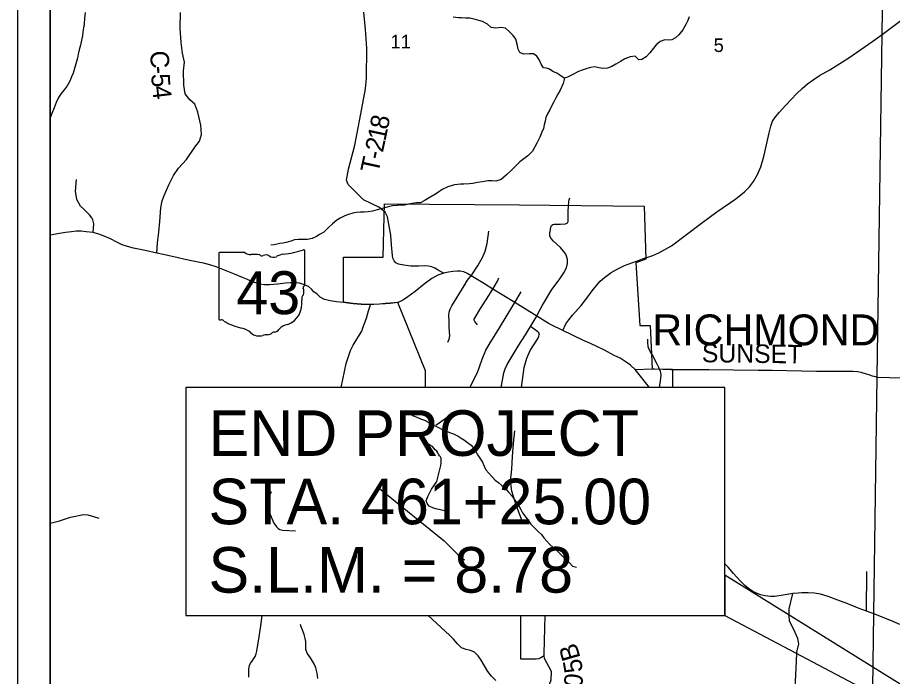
# Model space of a CAD drawing. Extents: x 0 to 34, y 0 to 22.
# Drawn here: x 2 to 4.685, y 18.266 to 20.29 of the extents above; entities that cross this region are included whole.
import ezdxf

# ---------------------------------------------------------------- set-up
doc = ezdxf.new("R2010")
doc.units = 0
for name, color, linetype in [('GM_X_City_Street', 7, 'Continuous'), ('GM_X_Corporation', 7, 'Continuous'), ('GM_X_Corporation_Text', 7, 'Continuous'), ('GM_X_County_Road', 7, 'Continuous'), ('GM_X_County_Road_Text', 7, 'Continuous'), ('GM_X_Minor_River', 7, 'Continuous'), ('GM_X_Section_Text', 7, 'Continuous'), ('GM_X_State_Location', 7, 'Continuous'), ('GM_X_State_Route', 7, 'Continuous'), ('GM_X_State_Shield', 7, 'Continuous'), ('GM_X_Township_Road', 7, 'Continuous'), ('GM_X_Township_Road_Text', 7, 'Continuous'), ('SH_Data', 7, 'Continuous'), ('SH_Text', 7, 'Continuous')]:
    doc.layers.add(name, color=color, linetype=linetype)

msp = doc.modelspace()

# ---------------------------------------------------------------- linework, layer by layer
at = {"layer": 'GM_X_City_Street'}
msp.add_line((3.5265, 19.4141), (3.5459, 19.447), dxfattribs=at)
for points in [[(3.4846, 19.1536), (3.4924, 19.1981), (3.4962, 19.2112), (3.503, 19.2244), (3.5365, 19.2801), (3.5585, 19.3154), (3.574, 19.3409), (3.5933, 19.3728), (3.6, 19.3862), (3.6114, 19.4065), (3.6402, 19.4546), (3.6625, 19.4844), (3.6769, 19.5054), (3.6847, 19.5208), (3.6881, 19.5342), (3.6883, 19.5462), (3.6858, 19.5542), (3.6832, 19.5631), (3.676, 19.5723), (3.666, 19.5839), (3.6452, 19.6034), (3.6374, 19.6109), (3.634, 19.6187), (3.6341, 19.6275), (3.6356, 19.6372), (3.6367, 19.6466), (3.639, 19.6514), (3.6429, 19.6542), (3.647, 19.6554), (3.6662, 19.6553), (3.6813, 19.6565), (3.6874, 19.659), (3.6899, 19.6636), (3.6902, 19.6691), (3.6902, 19.691), (3.6908, 19.7142), (3.6915, 19.7206), (3.6921, 19.7248), (3.6931, 19.7294), (3.6951, 19.7355)], [(3.308, 19.505), (3.2997, 19.5083), (3.2906, 19.5134), (3.281, 19.5195), (3.2718, 19.5241), (3.2614, 19.5263), (3.2502, 19.5271), (3.232, 19.5264), (3.2072, 19.5261), (3.1854, 19.5296), (3.1695, 19.5325), (3.1607, 19.5359), (3.1555, 19.5428), (3.1517, 19.5504), (3.1508, 19.5589), (3.1474, 19.5912), (3.1459, 19.6218), (3.1355, 19.6779)], [(3.3203, 19.293), (3.325, 19.3023), (3.3266, 19.3121), (3.3249, 19.3384), (3.3245, 19.3575), (3.3237, 19.3748), (3.3248, 19.3844), (3.3277, 19.3941), (3.3328, 19.4039), (3.3708, 19.4662), (3.3815, 19.4834), (3.3894, 19.4934), (3.3924, 19.4964), (3.4133, 19.5291), (3.4282, 19.5553), (3.4353, 19.5721), (3.4416, 19.5956), (3.4467, 19.6332)], [(3.4118, 19.3461), (3.404, 19.356), (3.4016, 19.3601), (3.4012, 19.3639), (3.421, 19.3958), (3.4392, 19.4246), (3.4586, 19.4558), (3.4732, 19.4805), (3.4773, 19.4903)], [(3.5469, 19.1536), (3.5553, 19.2151), (3.5627, 19.2436), (3.5733, 19.2668), (3.5974, 19.3053), (3.6001, 19.311), (3.6014, 19.3148), (3.6018, 19.3186), (3.5999, 19.3218), (3.5964, 19.3248), (3.574, 19.3409)]]:
    msp.add_lwpolyline(points, dxfattribs=at)
at = {"layer": 'GM_X_Corporation'}
for points in [[(4.6083, 17.0396), (4.6111, 17.2406), (4.6176, 17.7005), (4.6283, 18.459), (4.6386, 19.1863), (4.6534, 20.2382), (4.6627, 20.9), (2.1, 20.9), (2.1, 17.0396)], [(3.2523, 19.1536), (3.2519, 19.2051), (3.1667, 19.4149), (3.1438, 19.4123), (3.1289, 19.4114), (3.111, 19.4099), (3.0831, 19.4084), (3.0548, 19.4093), (3.0295, 19.4114), (3, 19.4152), (3.0007, 19.554), (3.1224, 19.5535), (3.1251, 19.6782), (3.1263, 19.7178), (3.5401, 19.7148), (3.6332, 19.713), (3.9236, 19.7105), (3.9285, 19.5472), (3.898, 19.5359), (3.9099, 19.3443), (3.9414, 19.3441), (3.9476, 19.2111), (4.0098, 19.2094), (4.0098, 19.1536)]]:
    msp.add_lwpolyline(points, dxfattribs=at)
at = {"layer": 'GM_X_County_Road'}
msp.add_line((3.9548, 19.2104), (4.005, 19.209), dxfattribs=at)
for points in [[(2.4276, 19.566), (2.4295, 19.5977), (2.4336, 19.6309), (2.4372, 19.6637), (2.44, 19.7048), (2.4437, 19.7263), (2.45, 19.7432), (2.4642, 19.7754), (2.4788, 19.8044), (2.4946, 19.8271), (2.5186, 19.854), (2.5445, 19.8914), (2.5589, 19.9096), (2.5649, 19.9302), (2.5624, 19.9586), (2.5536, 19.9991), (2.544, 20.0232), (2.5293, 20.0373), (2.5145, 20.0552), (2.5105, 20.0821), (2.5093, 20.1257), (2.5121, 20.1524), (2.5062, 20.1804), (2.5025, 20.2133), (2.4997, 20.2565), (2.4998, 20.3048)], [(3.8952, 19.2087), (3.9478, 19.2106), (3.9548, 19.2104)], [(4.005, 19.209), (4.01, 19.2088), (4.1215, 19.2085), (4.2726, 19.2064), (4.3156, 19.2063), (4.4068, 19.205), (4.4518, 19.2038), (4.5157, 19.204), (4.5647, 19.2034), (4.5789, 19.2025), (4.5881, 19.2005), (4.6045, 19.1954), (4.6127, 19.193), (4.6196, 19.1907), (4.6233, 19.1898)], [(4.6233, 19.1898), (4.6279, 19.1885), (4.6388, 19.1858), (4.7126, 19.1836)]]:
    msp.add_lwpolyline(points, dxfattribs=at)
at = {"layer": 'GM_X_Minor_River'}
for points in [[(2.2078, 20.3048), (2.2058, 20.2877), (2.2041, 20.269), (2.2028, 20.2576), (2.201, 20.2461), (2.1993, 20.2339), (2.1964, 20.2198), (2.1932, 20.2045), (2.1895, 20.19), (2.1863, 20.1767), (2.1838, 20.1652), (2.1794, 20.1476), (2.1754, 20.1331), (2.1707, 20.119), (2.1659, 20.1079), (2.1603, 20.0945), (2.1529, 20.0803), (2.1435, 20.068), (2.1342, 20.0561), (2.126, 20.0438), (2.1189, 20.0292), (2.1123, 20.0124), (2.1053, 19.9951), (2.1, 19.982)], [(4.0616, 20.2918), (4.0572, 20.2807), (4.0524, 20.27), (4.0416, 20.252), (4.03, 20.2369), (4.0191, 20.2269), (4.0085, 20.2214), (3.9975, 20.2197), (3.9864, 20.2211), (3.972, 20.2156), (3.9604, 20.2055), (3.9514, 20.1955), (3.9401, 20.1809), (3.9292, 20.1685), (3.916, 20.1604), (3.9065, 20.1602), (3.8957, 20.1711), (3.8802, 20.169), (3.8643, 20.1623), (3.8503, 20.1549), (3.8363, 20.1463), (3.8235, 20.1393), (3.8102, 20.1342), (3.7965, 20.1328), (3.7843, 20.1349), (3.7717, 20.1378), (3.758, 20.1365), (3.7448, 20.1325), (3.733, 20.1277), (3.7217, 20.1234), (3.7024, 20.1136), (3.688, 20.1069), (3.6774, 20.103), (3.6647, 20.1131), (3.6551, 20.119), (3.6429, 20.1242), (3.6329, 20.1309), (3.6234, 20.1346), (3.6138, 20.1356), (3.6068, 20.1469), (3.6021, 20.1583), (3.594, 20.1711), (3.5832, 20.1786), (3.5703, 20.1784), (3.5524, 20.1774), (3.5413, 20.1822), (3.537, 20.192), (3.533, 20.208), (3.529, 20.2227), (3.5209, 20.2348), (3.5085, 20.2464), (3.4977, 20.2566), (3.4848, 20.2594), (3.4681, 20.2565), (3.454, 20.2586), (3.4428, 20.2695), (3.4271, 20.2773), (3.4156, 20.2809), (3.4019, 20.2849), (3.3878, 20.2874), (3.3744, 20.288), (3.363, 20.2882), (3.3531, 20.2888), (3.3367, 20.2912)], [(3.6792, 20.1037), (3.675, 20.087), (3.6649, 20.0663), (3.6582, 20.0547), (3.6512, 20.0409), (3.6445, 20.0283), (3.6393, 20.0179), (3.6334, 20.0064), (3.6263, 19.9934), (3.6215, 19.9827), (3.619, 19.9716), (3.6168, 19.9597), (3.6139, 19.949), (3.6091, 19.9372), (3.6025, 19.9219), (3.5936, 19.9038), (3.5805, 19.8789), (3.5666, 19.865), (3.5538, 19.8561), (3.5421, 19.8468), (3.5305, 19.8356), (3.5162, 19.8209), (3.5008, 19.8066), (3.4842, 19.7926), (3.4676, 19.7867), (3.4569, 19.7885), (3.4436, 19.7879), (3.4269, 19.7854), (3.412, 19.7829), (3.3969, 19.78), (3.3874, 19.7791), (3.3695, 19.7781), (3.36, 19.7784), (3.341, 19.7758), (3.3307, 19.773), (3.3205, 19.7694), (3.3035, 19.762), (3.2922, 19.7538), (3.2805, 19.746), (3.2688, 19.739), (3.2582, 19.7332), (3.2476, 19.7265), (3.237, 19.7207), (3.2237, 19.7201), (3.2116, 19.7188), (3.2002, 19.7164), (3.1877, 19.7135), (3.1762, 19.7134), (3.1652, 19.7128), (3.1512, 19.7115), (3.1348, 19.7075), (3.1193, 19.7031), (3.1041, 19.6987), (3.0893, 19.6947), (3.0761, 19.693), (3.0643, 19.692), (3.0517, 19.6919), (3.0399, 19.6909), (3.0289, 19.6885), (3.016, 19.6849), (3.0043, 19.6805), (2.9907, 19.6735), (2.9805, 19.6673), (2.9665, 19.6564), (2.9534, 19.6437), (2.9399, 19.6309), (2.9289, 19.6247), (2.9176, 19.6169), (2.904, 19.611), (2.8903, 19.6078), (2.8762, 19.6076), (2.8618, 19.6078), (2.8504, 19.6068), (2.8386, 19.6032), (2.8242, 19.5992), (2.8147, 19.5972), (2.8048, 19.5956), (2.7874, 19.5919), (2.7775, 19.5902)], [(3.9333, 19.3015), (3.9334, 19.292), (3.9347, 19.2794), (3.9387, 19.2696), (3.9449, 19.2583), (3.9504, 19.2484), (3.9562, 19.2371), (3.9624, 19.2261), (3.9675, 19.2159), (3.9726, 19.2042), (3.9739, 19.192), (3.9733, 19.1817), (3.9695, 19.1536)], [(3.1915, 19.0827), (3.2027, 19.0733), (3.2149, 19.0663), (3.226, 19.0622), (3.2371, 19.0574), (3.2486, 19.053), (3.262, 19.046), (3.2742, 19.0389), (3.2915, 19.0304), (3.303, 19.0248), (3.3144, 19.0201), (3.3259, 19.0156), (3.3378, 19.0112), (3.3519, 19.0038), (3.3615, 18.9982), (3.3715, 18.9923), (3.3815, 18.9848), (3.3919, 18.9766), (3.4007, 18.9664), (3.4062, 18.9566), (3.4128, 18.9453), (3.4268, 18.9242), (3.4323, 18.9117), (3.437, 18.9011), (3.4462, 18.8909), (3.4555, 18.8804), (3.4663, 18.8695), (3.4767, 18.8609), (3.4867, 18.8531), (3.4963, 18.8441), (3.5067, 18.8324), (3.5168, 18.8211), (3.5238, 18.8109), (3.5315, 18.8008), (3.5389, 18.7898), (3.5443, 18.7793), (3.5502, 18.7683), (3.5591, 18.7566), (3.5668, 18.7465), (3.5754, 18.7344), (3.5842, 18.7246), (3.5981, 18.7111), (3.6081, 18.7018), (3.6155, 18.6916), (3.6244, 18.6814), (3.634, 18.6717), (3.644, 18.6623), (3.654, 18.6544), (3.6633, 18.6447), (3.6733, 18.6345), (3.6833, 18.6248), (3.6941, 18.6147), (3.7034, 18.6049), (3.7157, 18.6014)], [(3.4675, 18.254), (3.4548, 18.2671), (3.4436, 18.2814), (3.4327, 18.2992), (3.4226, 18.3165), (3.414, 18.3297), (3.4028, 18.341), (3.3902, 18.3461), (3.3772, 18.349), (3.3631, 18.3537), (3.3504, 18.3669), (3.3376, 18.3812), (3.3253, 18.3935), (3.2601, 18.4536)], [(2.9215, 18.2598), (2.9197, 18.2769), (2.9157, 18.2928), (2.9118, 18.3027), (2.9055, 18.3132), (2.8989, 18.3234), (2.8885, 18.3381), (2.8853, 18.3495), (2.8851, 18.3635), (2.8846, 18.3734), (2.8833, 18.3829), (2.8797, 18.3947), (2.8754, 18.4068), (2.871, 18.4185), (2.869, 18.4261)]]:
    msp.add_lwpolyline(points, dxfattribs=at)
at = {"layer": 'GM_X_State_Route'}
for points in [[(3.9496, 19.5592), (3.9687, 19.5667), (3.9862, 19.5776), (4.0066, 19.589), (4.0993, 19.6581), (4.1459, 19.6927), (4.2042, 19.733), (4.2309, 19.7545), (4.2469, 19.7694), (4.2589, 19.7858), (4.2711, 19.8081), (4.281, 19.8312), (4.2902, 19.8628), (4.2987, 19.8984), (4.3066, 19.9356), (4.3119, 19.9562), (4.3174, 19.9709), (4.326, 19.9845), (4.3386, 19.9995), (4.3558, 20.0184), (4.3739, 20.0382), (4.3912, 20.0561), (4.4077, 20.0714), (4.4249, 20.0862), (4.4418, 20.0985), (4.4611, 20.1112), (4.4927, 20.1293), (4.5515, 20.1661), (4.6251, 20.2166), (4.6536, 20.2377), (4.7192, 20.2863)], [(3.014, 19.4129), (3.0002, 19.4147), (2.9793, 19.4165), (2.9591, 19.4198), (2.9424, 19.4242), (2.9284, 19.4311), (2.9192, 19.4397), (2.9097, 19.4478), (2.9022, 19.4555), (2.893, 19.4632), (2.8805, 19.4686), (2.8659, 19.4737), (2.8548, 19.4751), (2.8462, 19.4754), (2.8365, 19.4754), (2.8227, 19.474), (2.7975, 19.4705), (2.7736, 19.4688), (2.7565, 19.469), (2.7433, 19.4712), (2.7313, 19.4745), (2.7203, 19.4782), (2.7054, 19.485), (2.6909, 19.4913), (2.6662, 19.5012), (2.6352, 19.5143), (2.6092, 19.5246), (2.5905, 19.5298), (2.5712, 19.5349), (2.5543, 19.5382), (2.5234, 19.5449), (2.4794, 19.5549), (2.4469, 19.562), (2.4276, 19.566), (2.3915, 19.5742), (2.3562, 19.5818), (2.3378, 19.5862), (2.3211, 19.5918), (2.3045, 19.5997), (2.2859, 19.6102), (2.2664, 19.6184), (2.2495, 19.6242), (2.2323, 19.6291), (2.2111, 19.6311), (2.1958, 19.6336), (2.1806, 19.6333), (2.1653, 19.6316), (2.1478, 19.6293), (2.1291, 19.6267), (2.1, 19.6216)], [(3.9023, 19.5426), (3.9183, 19.5482), (3.9409, 19.5559), (3.9496, 19.5592)], [(3.6733, 19.3285), (3.683, 19.3487), (3.6915, 19.3618), (3.7031, 19.3754), (3.7301, 19.4055), (3.7473, 19.4276), (3.7639, 19.4509), (3.7765, 19.4672), (3.788, 19.4798), (3.8013, 19.4914), (3.8218, 19.5064), (3.8424, 19.5184), (3.8632, 19.5285), (3.8854, 19.5366), (3.9023, 19.5426)], [(3.3819, 19.5029), (3.3811, 19.5035), (3.3702, 19.5084), (3.3589, 19.511), (3.349, 19.5111), (3.3356, 19.5095), (3.3222, 19.5075), (3.308, 19.505), (3.2899, 19.4989), (3.2712, 19.4882), (3.2479, 19.4704), (3.2205, 19.4486), (3.1978, 19.4317), (3.1846, 19.4224), (3.1811, 19.4208)], [(3.4331, 19.4714), (3.3924, 19.4964), (3.3819, 19.5029)], [(3.5265, 19.4141), (3.4586, 19.4558), (3.4331, 19.4714)], [(3.1811, 19.4208), (3.1669, 19.4144), (3.144, 19.4117), (3.1291, 19.4108), (3.1112, 19.4093), (3.0932, 19.4084)], [(3.0932, 19.4084), (3.0833, 19.4079), (3.055, 19.4088), (3.0297, 19.4108), (3.014, 19.4129)], [(3.388, 19.1536), (3.4117, 19.1998), (3.4177, 19.2171), (3.4256, 19.241), (3.4374, 19.2687), (3.4504, 19.2905), (3.4679, 19.3183), (3.4965, 19.3659), (3.5265, 19.4141)], [(3.6282, 19.351), (3.6179, 19.3569), (3.5933, 19.3728), (3.5265, 19.4141)], [(3.6733, 19.3285), (3.6377, 19.3457), (3.6282, 19.351)], [(3.7468, 19.2935), (3.7413, 19.2959), (3.7009, 19.315), (3.6733, 19.3285)], [(3.9396, 19.1536), (3.8952, 19.2087), (3.8811, 19.222), (3.8678, 19.2316), (3.8499, 19.2438), (3.8316, 19.2521), (3.8019, 19.2678), (3.776, 19.2807), (3.7468, 19.2935)], [(3.2843, 19.0376), (3.3112, 19.0577), (3.3149, 19.0608)], [(4.7079, 18.4261), (4.6818, 18.4369), (4.6285, 18.4585), (4.6055, 18.4666), (4.583, 18.4746), (4.548, 18.4889), (4.5178, 18.5003), (4.4881, 18.5121), (4.4647, 18.5186), (4.4449, 18.5222), (4.4269, 18.5233), (4.4071, 18.5235), (4.3954, 18.5225), (4.3792, 18.5207), (4.3493, 18.5155), (4.3238, 18.5114), (4.3106, 18.5116), (4.2948, 18.5135), (4.2807, 18.5173), (4.2678, 18.5217), (4.2562, 18.5272), (4.2432, 18.536), (4.2324, 18.5455), (4.2186, 18.559), (4.1973, 18.5824), (4.1806, 18.6014), (4.171, 18.6119)], [(2.7104, 18.2638), (2.7096, 18.2803), (2.71, 18.2898), (2.7115, 18.2996), (2.7154, 18.3076), (2.7197, 18.3136), (2.7254, 18.321), (2.7295, 18.3276), (2.7323, 18.3353), (2.7347, 18.344), (2.7365, 18.3573), (2.7398, 18.3745), (2.7471, 18.4213), (2.7512, 18.4536)]]:
    msp.add_lwpolyline(points, dxfattribs=at)
at = {"layer": 'GM_X_State_Shield'}
for p, q in [((2.6177, 19.5647), (2.6177, 19.3646)), ((2.6975, 19.5681), (2.6203, 19.5681)), ((2.8814, 19.4684), (2.8814, 19.5731)), ((2.8814, 19.4684), (2.8814, 19.4684))]:
    msp.add_line(p, q, dxfattribs=at)
for centre, radius, start, end in [((2.7875, 19.841), 0.2796, 275.8445, 288.9065), ((2.8785, 19.5735), 0.00294, 351.8621, 97.738), ((2.6208, 19.5651), 0.00305, 98.1301, 188.1301), ((2.7159, 19.5914), 0.0296, 231.6195, 271.1119), ((2.7258, 19.4558), 0.1064, 80.4867, 94.9883), ((2.7499, 19.5661), 0.00855, 219.7921, 297.1024), ((2.7625, 19.543), 0.0178, 54.4667, 119.1411), ((2.7854, 19.5747), 0.0214, 233.8562, 294.8282), ((2.8231, 19.507), 0.0563, 97.3462, 120.7689), ((2.8783, 19.468), 0.00314, 289.6038, 7.7341), ((2.8807, 19.4607), 0.00454, 107.944, 210.337), ((2.8518, 19.4475), 0.0273, 340.033, 23.6496), ((2.8031, 19.4113), 0.0699, 292.3089, 8.9858), ((2.8919, 19.4246), 0.0198, 136.8065, 186.9296), ((2.6208, 19.3641), 0.00308, 171.9584, 258.3066), ((2.6212, 19.3846), 0.0235, 267.339, 280.6039), ((2.6261, 19.353), 0.00848, 29.7484, 93.2717), ((2.7331, 19.5328), 0.2019, 240.4129, 257.1985), ((2.6729, 19.2747), 0.0632, 47.1842, 75.836), ((2.8326, 19.3084), 0.0383, 94.4031, 142.5768), ((2.7412, 19.352), 0.0401, 230.7004, 286.2918), ((2.7644, 19.2828), 0.0329, 85.6951, 111.2099), ((2.7673, 19.337), 0.0214, 268.777, 315.5493), ((2.7867, 19.3177), 0.00601, 65.7517, 132.6484), ((2.7841, 19.3452), 0.0226, 282.8732, 323.2771)]:
    msp.add_arc(centre, radius, start, end, dxfattribs=at)
at = {"layer": 'GM_X_Township_Road'}
msp.add_line((4.6055, 18.4666), (4.6064, 18.5883), dxfattribs=at)
for points in [[(3.1355, 19.6779), (3.1281, 19.6923), (3.1085, 19.7071), (3.0621, 19.7299), (3.0402, 19.7509), (3.0149, 19.7765), (3.0096, 19.7903), (3.0156, 19.8242), (3.0354, 19.898), (3.0504, 19.9778), (3.0679, 20.071), (3.0714, 20.1035), (3.0716, 20.1953), (3.0679, 20.2532), (3.0628, 20.3057)], [(2.2323, 19.6291), (2.2338, 19.6566), (2.2316, 19.6682), (2.2281, 19.6742), (2.2205, 19.6842), (2.2033, 19.7011), (2.1938, 19.71), (2.1821, 19.7308), (2.1783, 19.7563), (2.1806, 19.7925)], [(2.9934, 19.1536), (3.0086, 19.2269), (3.0223, 19.2673), (3.0302, 19.2832), (3.0442, 19.3066), (3.0563, 19.3266), (3.0594, 19.3367), (3.0707, 19.3662), (3.0773, 19.3891), (3.0833, 19.4079)], [(3.5298, 18.7954), (3.5272, 18.8024), (3.5166, 18.835), (3.5127, 18.8672), (3.5172, 18.9032), (3.5186, 18.9418), (3.522, 18.9817), (3.5267, 19.021)], [(3.3117, 18.7751), (3.2875, 18.7802), (3.2762, 18.7833), (3.2637, 18.7893), (3.2572, 18.7976), (3.2543, 18.8053), (3.2589, 18.8192), (3.2702, 18.841), (3.2776, 18.8517), (3.2871, 18.8654), (3.2988, 18.9142), (3.3003, 18.9226), (3.3005, 18.9302), (3.2999, 18.9363), (3.2984, 18.9404), (3.2951, 18.944), (3.2923, 18.9488), (3.2902, 18.9529), (3.2867, 18.9585), (3.282, 18.9625), (3.2776, 18.9673), (3.2734, 18.9721), (3.2677, 18.975), (3.2615, 18.9791), (3.2389, 19.0019)], [(2.7782, 18.8334), (2.7667, 18.8063), (2.7648, 18.7976), (2.7654, 18.7901), (2.7682, 18.7808), (2.7758, 18.7641), (2.787, 18.7368), (2.7955, 18.7251), (2.7998, 18.7206), (2.8054, 18.7173), (2.8134, 18.7159), (2.8531, 18.7139)], [(3.1059, 18.8476), (3.3094, 18.6829), (3.3512, 18.6412), (3.3721, 18.6248)], [(3.5511, 18.7383), (3.5468, 18.749), (3.5298, 18.7954)], [(2.1, 18.7366), (2.1284, 18.744), (2.1623, 18.755), (2.2024, 18.7637), (2.2156, 18.7623), (2.2328, 18.757), (2.2501, 18.7519)], [(4.3684, 18.4543), (4.3679, 18.474), (4.3792, 18.5207)], [(3.6162, 18.3292), (3.6061, 18.3232), (3.5997, 18.3206), (3.5922, 18.3198), (3.5443, 18.319), (3.5445, 18.4536)], [(3.5681, 17.8746), (3.5995, 17.9538), (3.6169, 17.9925), (3.6336, 18.03), (3.6357, 18.071), (3.625, 18.0924), (3.6156, 18.107), (3.6152, 18.1419), (3.6196, 18.2043), (3.6375, 18.2563), (3.6384, 18.2817), (3.6175, 18.3219), (3.6162, 18.3292), (3.6164, 18.3366), (3.6197, 18.4536)], [(4.3915, 18.337), (4.3916, 18.3406), (4.3983, 18.3669), (4.3949, 18.3824), (4.3826, 18.4102), (4.3687, 18.4365), (4.3684, 18.4543)], [(4.3703, 18.003), (4.366, 18.0229), (4.3674, 18.0363), (4.3813, 18.0762), (4.3895, 18.1037), (4.3911, 18.1353), (4.392, 18.1782), (4.3854, 18.2224), (4.3875, 18.2509), (4.39, 18.2923), (4.3915, 18.337)]]:
    msp.add_lwpolyline(points, dxfattribs=at)
at = {"layer": 'SH_Data'}
msp.add_line((2, 21), (2, 14), dxfattribs=at)
for points in [[(2.1, 20.9), (8.9, 20.9), (8.9, 14.1), (2.1, 14.1)], [(4.171, 18.4536), (5.5002, 17.7508), (4.171, 18.5769)]]:
    msp.add_lwpolyline(points, close=True, dxfattribs=at)
at = {"layer": 'SH_Text'}
msp.add_lwpolyline([(2.5162, 18.4536), (4.171, 18.4536), (4.171, 19.1536), (2.5162, 19.1536)], close=True, dxfattribs=at)

# ---------------------------------------------------------------- texts
at = {"layer": 'GM_X_Corporation_Text'}
msp.add_text('RICHMOND', height=0.0947, rotation=0, dxfattribs=at).set_placement((3.9485, 19.2832))
at = {"layer": 'GM_X_County_Road_Text'}
for s, height, rotation, p in [('C', 0.0568, 272.5886, (2.4071, 20.1868)), ('5', 0.0568, 273.4297, (2.4103, 20.116)), ('-', 0.0568, 272.7603, (2.4092, 20.14)), ('4', 0.0568, 276.7221, (2.4127, 20.0775)), ('SUNSET', 0.05682, 359.2744, (4.1, 19.2313))]:
    msp.add_text(s, height=height, rotation=rotation, dxfattribs=at).set_placement(p)
at = {"layer": 'GM_X_Section_Text'}
for s, height, p in [('11', 0.04186, (3.1447, 20.1948)), ('5', 0.0419, (4.1364, 20.1837))]:
    msp.add_text(s, height=height, rotation=0, dxfattribs=at).set_placement(p)
at = {"layer": 'GM_X_State_Location'}
for s in ['s', 'r']:
    msp.add_text(s, height=0.000189, dxfattribs=at).set_placement((2.7466, 19.4513))
msp.add_text('43', height=0.000189, rotation=0, dxfattribs=at).set_placement((2.6989, 19.4375))
at = {"layer": 'GM_X_State_Shield'}
msp.add_text('43', height=0.13184, dxfattribs=at).set_placement((2.6714, 19.3787))
at = {"layer": 'GM_X_Township_Road_Text'}
for s, rotation, p in [('8', 78.9824, (3.1361, 19.9432)), ('1', 78.0206, (3.1287, 19.9079)), ('2', 77.7701, (3.1212, 19.8734)), ('-', 77.7048, (3.1162, 19.8506)), ('T', 77.6915, (3.1072, 19.809)), ('B', 106.0988, (3.7283, 18.3237)), ('5', 99.5339, (3.7357, 18.2822)), ('0', 83.0426, (3.7319, 18.2297))]:
    msp.add_text(s, height=0.0568, rotation=rotation, dxfattribs=at).set_placement(p)
at = {"layer": 'SH_Text'}
for s, p in [('END PROJECT', (2.5862, 18.9436)), ('STA. 461+25.00', (2.5862, 18.7336)), ('S.L.M. = 8.78', (2.5862, 18.5236))]:
    msp.add_text(s, height=0.14, dxfattribs=at).set_placement(p)

doc.saveas('drawing.dxf')
